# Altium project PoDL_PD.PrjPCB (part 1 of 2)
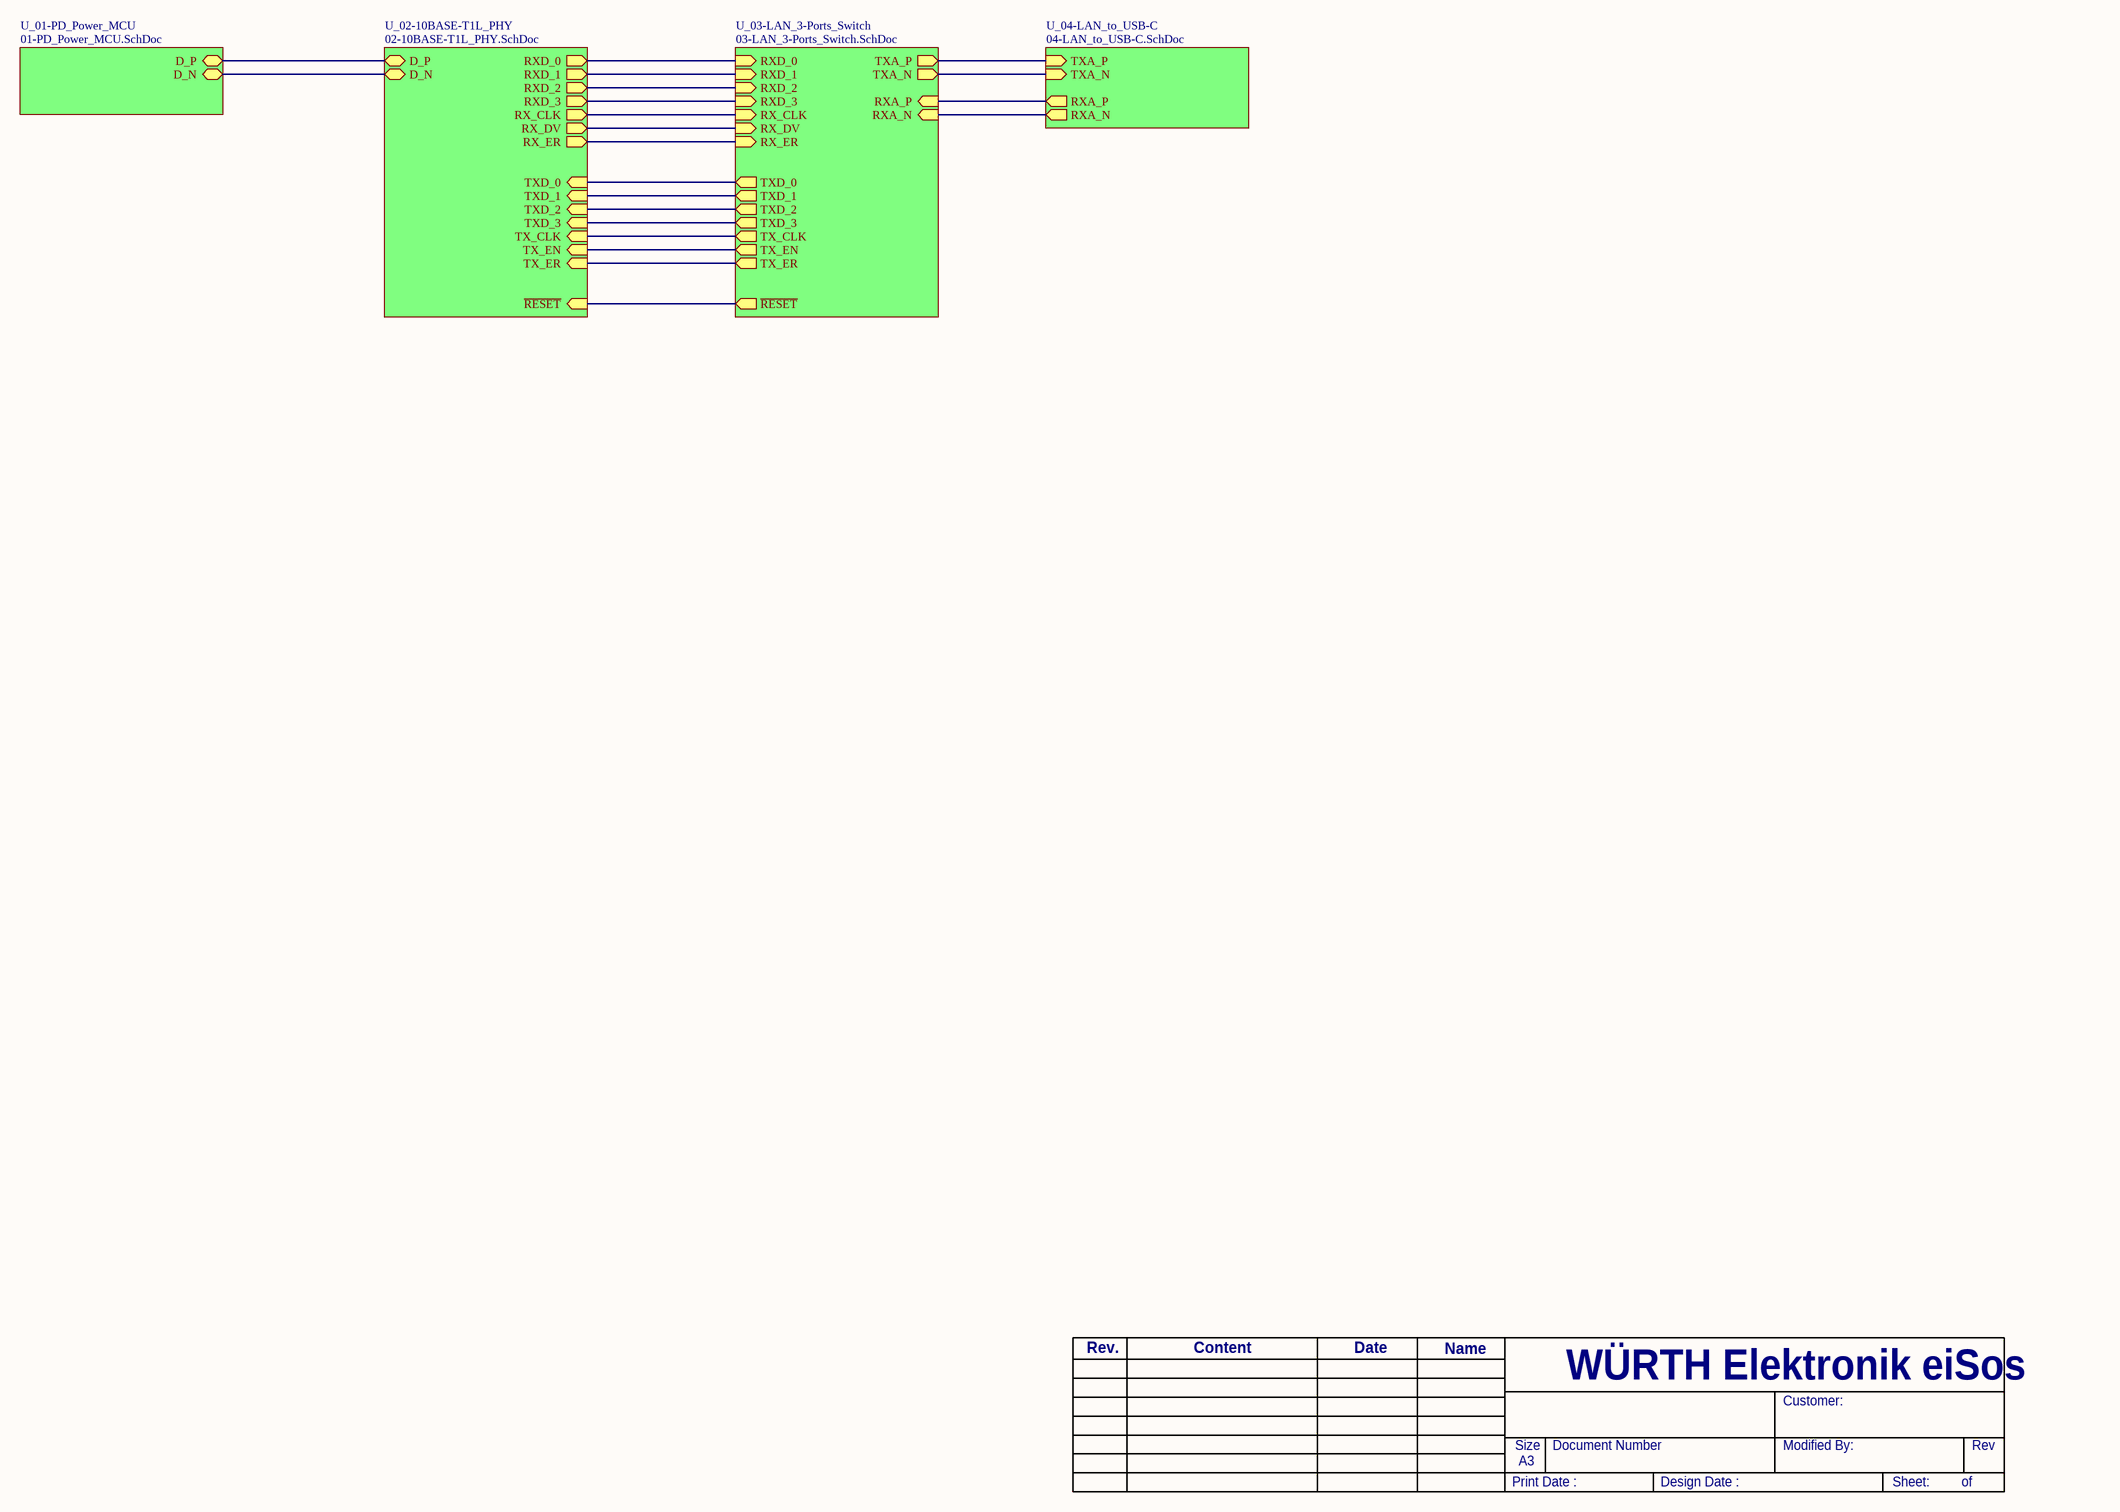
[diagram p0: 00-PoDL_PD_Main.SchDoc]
5 sheets, 346 parts. Net scope: hierarchical (ports join the sheet entries above them; power ports are global).
Board file: PoDL_PD_V15.PcbDoc
Sheets:
  00-PoDL_PD_Main.SchDoc
    U_01-PD_Power_MCU = 01-PD_Power_MCU.SchDoc
    U_02-10BASE-T1L_PHY = 02-10BASE-T1L_PHY.SchDoc
    U_03-LAN_3-Ports_Switch = 03-LAN_3-Ports_Switch.SchDoc
    U_04-LAN_to_USB-C = 04-LAN_to_USB-C.SchDoc

## Sheet 00-PoDL_PD_Main.SchDoc: PD Main
size A2; Date: Mon 1st Aug, 2020; CompanyName: RGT Supply and Service Ltd.; Engineer: Nattawut; Address1: 285/95 M.3 T.Tonpao Sankampaeng; Address2: Chiangmai 50130 Thailand Tel.+66 89 1645339; Revision: 1.5; SheetNumber: 0; SheetTotal: 4; ContentRev1: Original Document; dateREV1: 01-01-2023; NameRev1: Nattawut; NameRev3: Nattawut; NameRev2: Nattawut; NameRev4: Nattawut; NameRev5: Nattawut; NameRev6: Nattawut; dateREV2: 20-04-2023; dateREV3: 04-11-2023; dateREV4: 14-05-2024; dateREV5: 05-07-2024; dateREV6: 16-09-2024; ContentRev2: Change to AD controller; ContentRev3: Update Power Coupling; ContentRev4: Improve for EMC ability; ContentRev5: Add D31, Replace FB7 to R164; ContentRev6: Improve for EMC ability; Rev1: 1.0; Rev2: 1.1; Rev3: 1.2; Rev4: 1.3; Rev5: 1.4; Rev6: 1.5; Project: PoDL; PageSetup: Record=PageOptions¦CenterHorizontal=True¦CenterVertical=True¦PrintScale=0.73¦XCorrection=1.00¦YCorrection=1.00¦PrintKind=0¦BorderSize=5000000¦LeftOffset=0¦BottomOffset=0¦Orientation=2¦PaperLength=1000¦PaperWidth=1000¦Scale=100¦PaperSource=7¦PrintQuality=-3¦MediaType=1¦DitherType=10¦PrintScaleMode=1¦PaperKind=A3¦PaperIndex=8

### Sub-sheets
U_01-PD_Power_MCU = 01-PD_Power_MCU.SchDoc: D_P (bidir), D_N (bidir)
U_02-10BASE-T1L_PHY = 02-10BASE-T1L_PHY.SchDoc: RXD_0 (out), RXD_1 (out), RXD_2 (out), RXD_3 (out), RX_CLK (out), RX_DV (out), RX_ER (out), TX_ER (in), TX_EN (in), TX_CLK (in), TXD_0 (in), TXD_1 (in), TXD_3 (in), TXD_2 (in), ~{RESET} (in), D_P (bidir), D_N (bidir)
U_03-LAN_3-Ports_Switch = 03-LAN_3-Ports_Switch.SchDoc: TXA_N (out), TXA_P (out), RXA_N (in), RXA_P (in), ~{RESET} (out), RXD_1 (in), TXD_2 (out), TXD_3 (out), RX_ER (in), RX_DV (in), RX_CLK (in), RXD_0 (in), RXD_3 (in), TXD_0 (out), TX_EN (out), TX_ER (out), RXD_2 (in), TXD_1 (out), TX_CLK (out)
U_04-LAN_to_USB-C = 04-LAN_to_USB-C.SchDoc: TXA_N (in), TXA_P (in), RXA_N (out), RXA_P (out)

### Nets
D_N: sheet U_01-PD_Power_MCU/D_N, sheet U_02-10BASE-T1L_PHY/D_N
D_P: sheet U_01-PD_Power_MCU/D_P, sheet U_02-10BASE-T1L_PHY/D_P
P0_INCLK: sheet U_02-10BASE-T1L_PHY/RX_CLK, sheet U_03-LAN_3-Ports_Switch/RX_CLK
P0_IND0: sheet U_02-10BASE-T1L_PHY/RXD_0, sheet U_03-LAN_3-Ports_Switch/RXD_0
P0_IND1: sheet U_02-10BASE-T1L_PHY/RXD_1, sheet U_03-LAN_3-Ports_Switch/RXD_1
P0_IND2: sheet U_02-10BASE-T1L_PHY/RXD_2, sheet U_03-LAN_3-Ports_Switch/RXD_2
P0_IND3: sheet U_02-10BASE-T1L_PHY/RXD_3, sheet U_03-LAN_3-Ports_Switch/RXD_3
P0_INDV: sheet U_02-10BASE-T1L_PHY/RX_DV, sheet U_03-LAN_3-Ports_Switch/RX_DV
P0_INER: sheet U_02-10BASE-T1L_PHY/RX_ER, sheet U_03-LAN_3-Ports_Switch/RX_ER
P0_OUT/REF_CLK_MODE0: sheet U_02-10BASE-T1L_PHY/TX_CLK, sheet U_03-LAN_3-Ports_Switch/TX_CLK
P0_OUTD0_MODE1: sheet U_02-10BASE-T1L_PHY/TXD_0, sheet U_03-LAN_3-Ports_Switch/TXD_0
P0_OUTD1_MODE2: sheet U_02-10BASE-T1L_PHY/TXD_1, sheet U_03-LAN_3-Ports_Switch/TXD_1
P0_OUTD2_MODE3: sheet U_02-10BASE-T1L_PHY/TXD_2, sheet U_03-LAN_3-Ports_Switch/TXD_2
P0_OUTD3: sheet U_02-10BASE-T1L_PHY/TXD_3, sheet U_03-LAN_3-Ports_Switch/TXD_3
P0_OUTDV: sheet U_02-10BASE-T1L_PHY/TX_EN, sheet U_03-LAN_3-Ports_Switch/TX_EN
P0_OUTER_SPEED: sheet U_02-10BASE-T1L_PHY/TX_ER, sheet U_03-LAN_3-Ports_Switch/TX_ER
~{RESET}: sheet U_02-10BASE-T1L_PHY/~{RESET}, sheet U_03-LAN_3-Ports_Switch/~{RESET}
RXA_N: sheet U_03-LAN_3-Ports_Switch/RXA_N, sheet U_04-LAN_to_USB-C/RXA_N
RXA_P: sheet U_03-LAN_3-Ports_Switch/RXA_P, sheet U_04-LAN_to_USB-C/RXA_P
TXA_N: sheet U_03-LAN_3-Ports_Switch/TXA_N, sheet U_04-LAN_to_USB-C/TXA_N
TXA_P: sheet U_03-LAN_3-Ports_Switch/TXA_P, sheet U_04-LAN_to_USB-C/TXA_P

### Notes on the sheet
- Rev.
- Content
- Date
- Name
- WÜRTH Elektronik eiSos
- Customer:
- Print Date :
- Size
- A3
- Document Number
- Design Date :
- Modified By:
- Sheet:
- of
- Rev

## Sheet 01-PD_Power_MCU.SchDoc: PD Power & MCU
size A2; Date: Mon 1st Aug, 2020; CompanyName: RGT Supply and Service Ltd.; Engineer: Nattawut; Address1: 285/95 M.3 T.Tonpao Sankampaeng; Address2: Chiangmai 50130 Thailand Tel.+66 89 1645339; Revision: 1.5; SheetNumber: 1; SheetTotal: 4; ContentRev1: Original Document; dateREV1: 01-01-2023; NameRev1: Nattawut; NameRev3: Nattawut; NameRev2: Nattawut; NameRev4: Nattawut; NameRev5: Nattawut; NameRev6: Nattawut; dateREV2: 20-04-2023; dateREV3: 04-11-2023; dateREV4: 14-05-2024; dateREV5: 05-07-2024; dateREV6: 16-09-2024; ContentRev2: Change to AD controller; ContentRev3: Update Power Coupling; ContentRev4: Improve for EMC ability; ContentRev5: Add D31, Replace FB7 to R164; ContentRev6: Improve for EMC ability; Rev1: 1.0; Rev2: 1.1; Rev3: 1.2; Rev4: 1.3; Rev5: 1.4; Rev6: 1.5; Project: PoDL; PageSetup: Record=PageOptions¦CenterHorizontal=True¦CenterVertical=True¦PrintScale=0.73¦XCorrection=1.00¦YCorrection=1.00¦PrintKind=0¦BorderSize=5000000¦LeftOffset=0¦BottomOffset=0¦Orientation=2¦PaperLength=1000¦PaperWidth=1000¦Scale=100¦PaperSource=7¦PrintQuality=-3¦MediaType=1¦DitherType=10¦PrintScaleMode=1¦PaperKind=A3¦PaperIndex=8
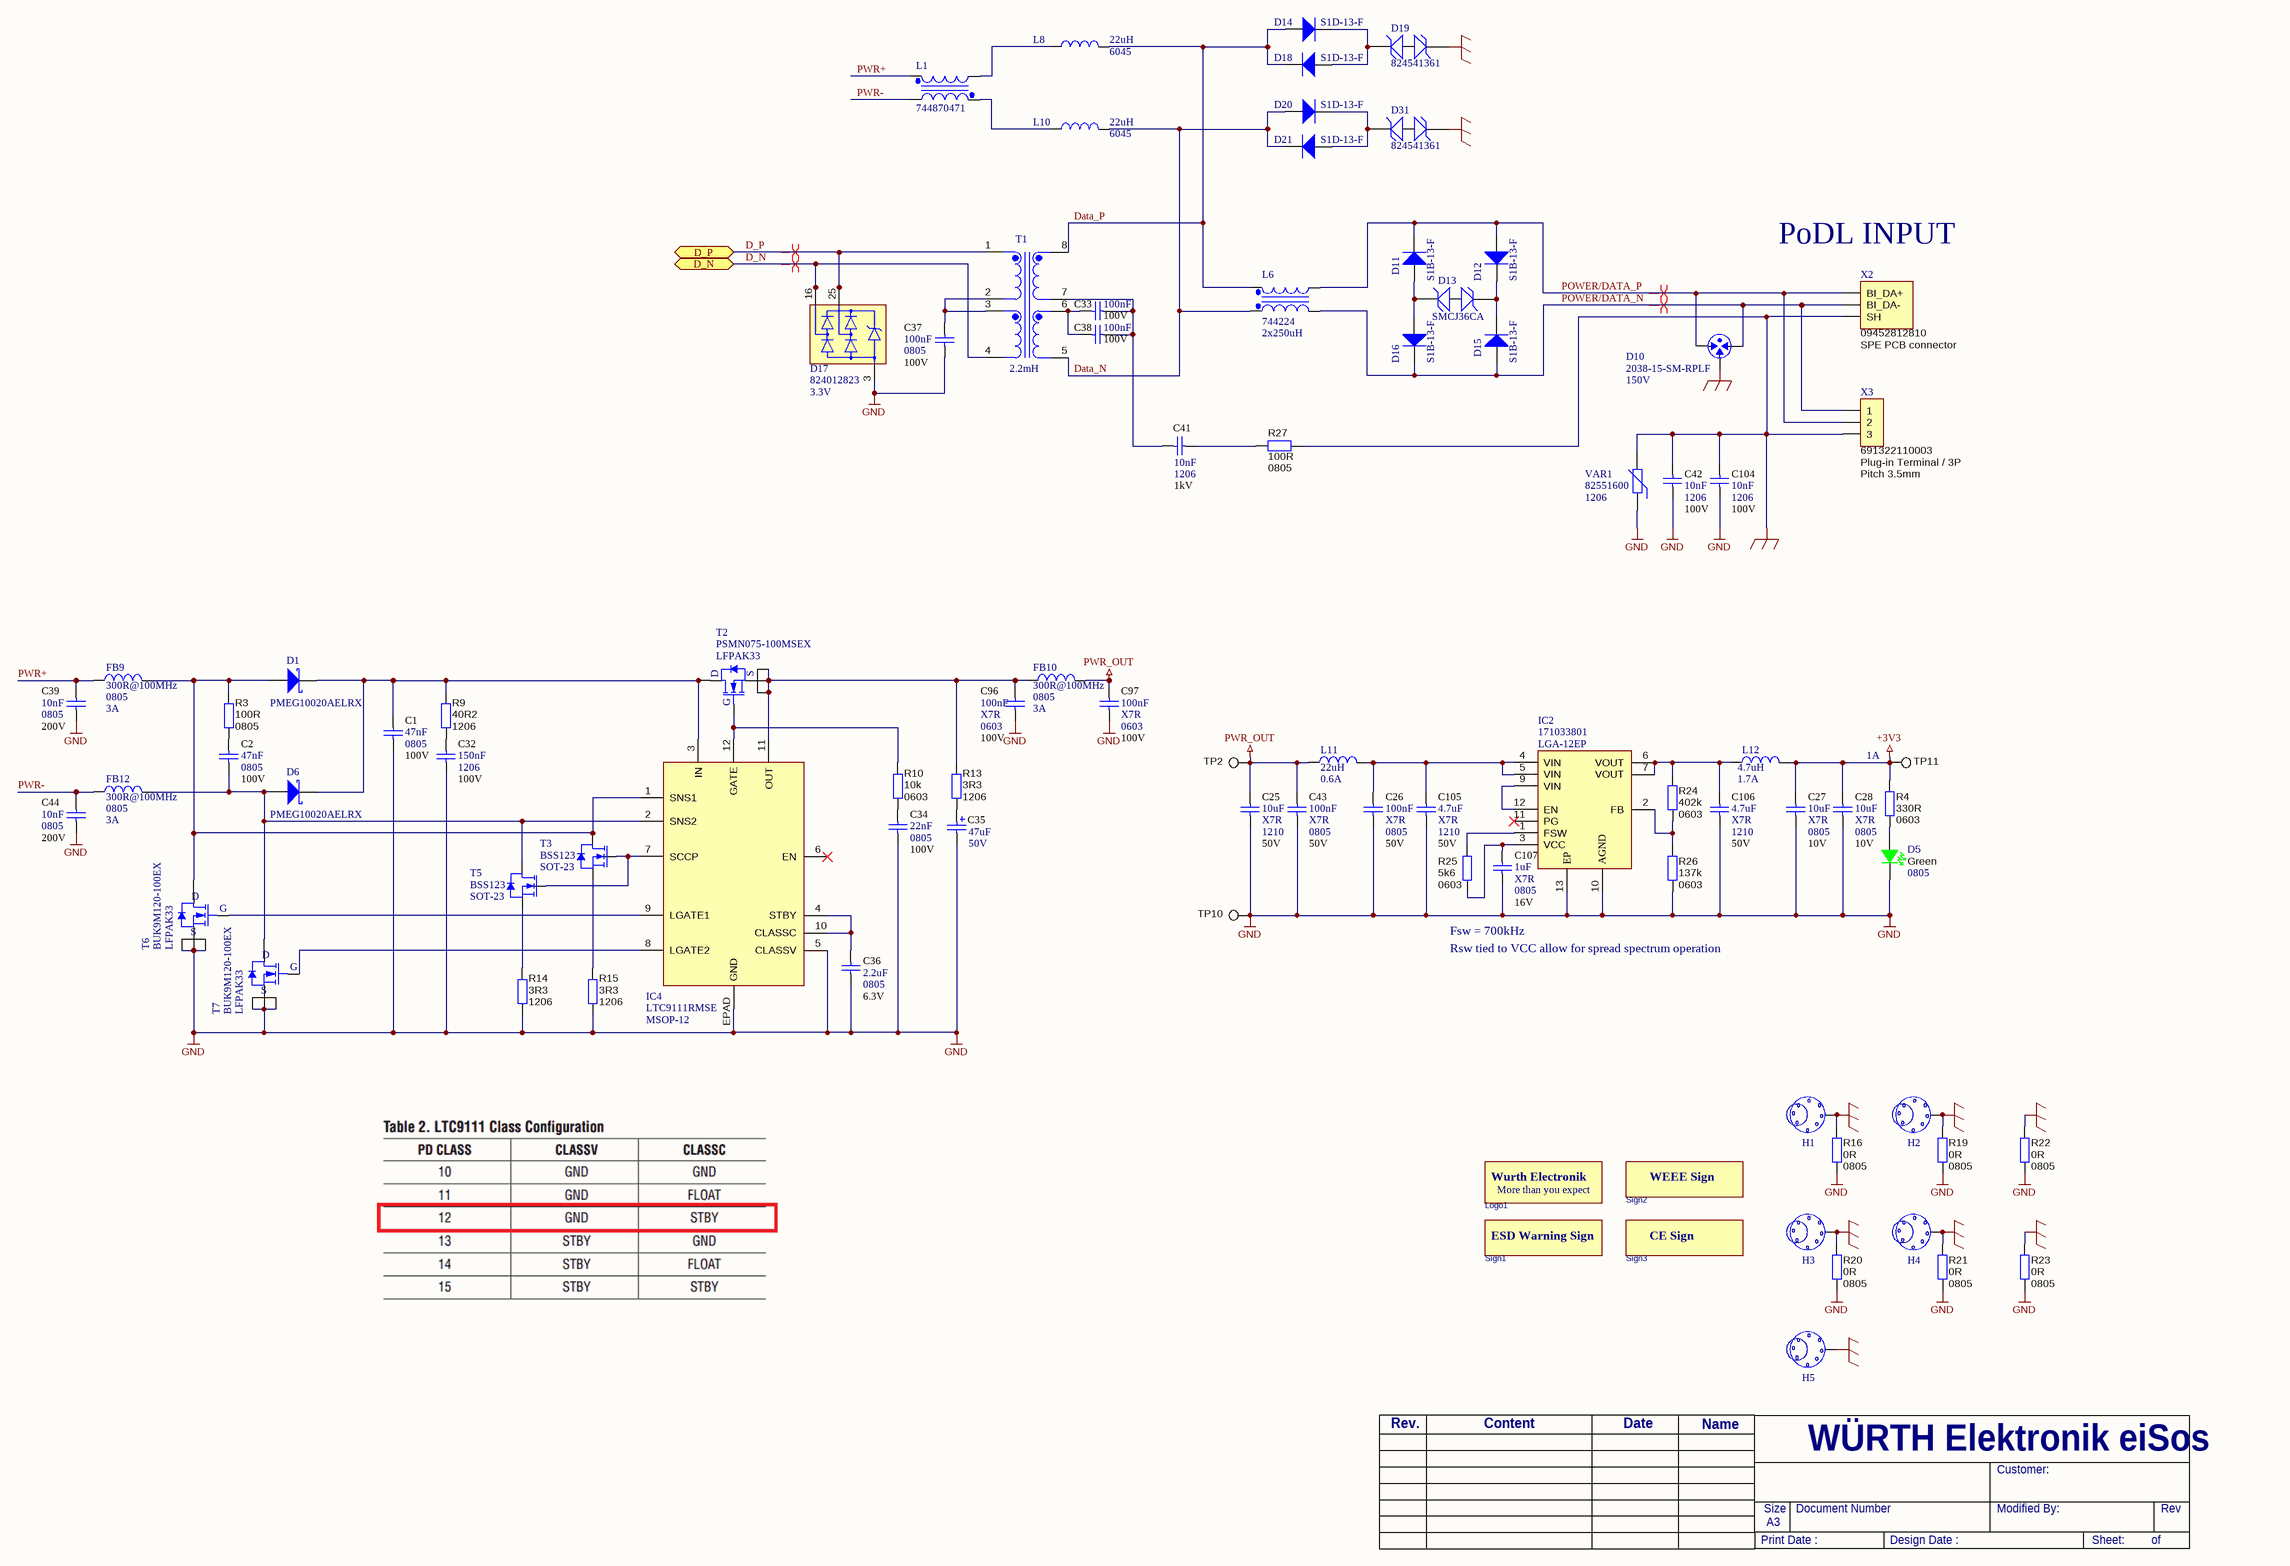
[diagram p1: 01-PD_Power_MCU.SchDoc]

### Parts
C1  value 47nF  VDC_V: 100V  PackageReference: 0805  [CC2012-0805]  (hidden comment: 885012207126)
C2  value 47nF  VDC_V: 100V  PackageReference: 0805  [CC2012-0805]  (hidden comment: 885012207126)
C25  value 10uF  VDC_V: 50V  PackageReference: 1210  Dielectric: X7R  [CC3225-1210]  (hidden comment: 885012209073)
C26  value 100nF  VDC_V: 50V  PackageReference: 0805  Dielectric: X7R  [CC2012-0805]  (hidden comment: 885012207098)
C27  value 10uF  VDC_V: 10V  PackageReference: 0805  Dielectric: X7R  [CC2012-0805]  (hidden comment: 885012207026)
C28  value 10uF  VDC_V: 10V  PackageReference: 0805  Dielectric: X7R  [CC2012-0805]  (hidden comment: 885012207026)
C32  value 150nF  PackageReference: 1206  VDC_V: 100V  [CC3216-1206]  (hidden comment: 885012208119)
C33  value 100nF  VDC_V: 100V  [CC1608-0603]  (hidden comment: 885012206120)
C34  value 22nF  VDC_V: 100V  PackageReference: 0805  [CC2012-0805]  (hidden comment: 885012207124)
C35  value 47uF  VDC_V: 50V  [SMT 6.3mmx7.7mm - WE]  (hidden comment: 865080645012)
C36  value 2.2uF  VDC_V: 6.3V  PackageReference: 0805  [CC2012-0805]  (hidden comment: 885012207001)
C37  value 100nF  VDC_V: 100V  PackageReference: 0805  [CC2012-0805]  (hidden comment: 885012207128)
C38  value 100nF  VDC_V: 100V  [CC1608-0603]  (hidden comment: 885012206120)
C39  value 10nF  VDC_V: 200V  PackageReference: 0805  [CC2012-0805]  (hidden comment: 885342207005)
C41  value 10nF  PackageReference: 1206  VDC_V: 1kV  [CC3216-1206]  (hidden comment: 885342208021)
C42  value 10nF  PackageReference: 1206  VDC_V: 100V  [CC3216-1206]  (hidden comment: 885012208112)
C43  value 100nF  VDC_V: 50V  PackageReference: 0805  Dielectric: X7R  [CC2012-0805]  (hidden comment: 885012207098)
C44  value 10nF  VDC_V: 200V  PackageReference: 0805  [CC2012-0805]  (hidden comment: 885342207005)
C96  value 100nF  VDC_V: 100V  PackageReference: 0603  Dielectric: X7R  [CC1608-0603]  (hidden comment: 885012206120)
C97  value 100nF  VDC_V: 100V  PackageReference: 0603  Dielectric: X7R  [CC1608-0603]  (hidden comment: 885012206120)
C104  value 10nF  PackageReference: 1206  VDC_V: 100V  [CC3216-1206]  (hidden comment: 885012208112)
C105  value 4.7uF  VDC_V: 50V  PackageReference: 1210  Dielectric: X7R  [CC3225-1210]  (hidden comment: 885012209048)
C106  value 4.7uF  VDC_V: 50V  PackageReference: 1210  Dielectric: X7R  [CC3225-1210]  (hidden comment: 885012209048)
C107  value 1uF  VDC_V: 16V  PackageReference: 0805  Dielectric: X7R  [CC2012-0805]  (hidden comment: 885012207051)
D1  PMEG10020AELRX  [SOD-123FL]
D5  value Green  PackageReference: 0805  [LED2012 (0805) - Green]  (hidden comment: 150080VS75000)
D6  PMEG10020AELRX  [SOD-123FL]
D10  value 150V  [2038-xx]  (hidden comment: 2038-15-SM-RPLF)
D11  S1B-13-F  [SMA/DO-214AC]
D12  S1B-13-F  [SMA/DO-214AC]
D13  SMCJ36CA  [SMC/DO-214AB]
D14  S1D-13-F  [SMA/DO-214AC]
D15  S1B-13-F  [SMA/DO-214AC]
D16  S1B-13-F  [SMA/DO-214AC]
D17  Voltage: 3.3V  [DFN1210-6L 1.2X1.0]  (hidden comment: 824012823)
D18  S1D-13-F  [SMA/DO-214AC]
D19  824541361  [SMC/DO-214AB]
D20  S1D-13-F  [SMA/DO-214AC]
D21  S1D-13-F  [SMA/DO-214AC]
D31  824541361  [SMC/DO-214AB]
FB9  value 300R@100MHz  PackageReference: 0805  I DC: 3A  [CF2012-0805]  (hidden comment: 742792031)
FB10  value 300R@100MHz  PackageReference: 0805  I DC: 3A  [CF2012-0805]  (hidden comment: 742792031)
FB12  value 300R@100MHz  PackageReference: 0805  I DC: 3A  [CF2012-0805]  (hidden comment: 742792031)
H1  Hole M3 with Vias  [M3_VIA]  (value not drawn)
H2  Hole M3 with Vias  [M3_VIA]  (value not drawn)
H3  Hole M3 with Vias  [M3_VIA]  (value not drawn)
H4  Hole M3 with Vias  [M3_VIA]  (value not drawn)
H5  Hole M3 with Vias  [M3_VIA]  (value not drawn)
IC2  PackageReference: LGA-12EP  [MAGI³C-VDRM_LGA-12EP]  (hidden comment: 171033801)
IC4  value LTC9111RMSE  PackageReference: MSOP-12  [MSOP-12 PAD]  (hidden comment: LTC9111RMSE#PBF)
L1  PartNumber: 744870471  [Inductor_WE-DD 1280]  (hidden comment: 744870471_(2))
L6  value 2x250uH  [Inductor_WE-SL2]  (hidden comment: 744224)
L8  value 22uH  PackageReference: 6045  [Inductor_WE-LQS 6045]  (hidden comment: 74404064220)
L10  value 22uH  PackageReference: 6045  [Inductor_WE-LQS 6045]  (hidden comment: 74404064220)
L11  value 22uH  I DC: 0.6A  [Inductor_WE-LQS 3015]  (hidden comment: 74404032220)
L12  value 4.7uH  I DC: 1.7A  [Inductor_WE-LQS-4018]  (hidden comment: 74404042047)
Logo1  Wurth_994x400  [Wurth_994x400]  (value not drawn)  (no BOM)
R3  value 100R  PackageReference: 0805  [CR2012-0805]  (hidden comment: 560112120020)
R4  value 330R  PackageReference: 0603  [CR1608-0603]  (hidden comment: 560112116020)
R9  value 40R2  PackageReference: 1206  [CR3216-1206]  (hidden comment: RC1206FR-0740R2L)
R10  value 10k  PackageReference: 0603  [CR1608-0603]  (hidden comment: 560112116005)
R13  value 3R3  PackageReference: 1206  [CR3216-1206]  (hidden comment: RC1206FR-073R3L)
R14  value 3R3  PackageReference: 1206  [CR3216-1206]  (hidden comment: RC1206FR-073R3L)
R15  value 3R3  PackageReference: 1206  [CR3216-1206]  (hidden comment: RC1206FR-073R3L)
R16  value 0R  PackageReference: 0805  [CR2012-0805]  (hidden comment: RC0805JR-070RL)
R19  value 0R  PackageReference: 0805  [CR2012-0805]  (hidden comment: RC0805JR-070RL)
R20  value 0R  PackageReference: 0805  [CR2012-0805]  (hidden comment: RC0805JR-070RL)
R21  value 0R  PackageReference: 0805  [CR2012-0805]  (hidden comment: RC0805JR-070RL)
R22  value 0R  PackageReference: 0805  [CR2012-0805]  (hidden comment: RC0805JR-070RL)
R23  value 0R  PackageReference: 0805  [CR2012-0805]  (hidden comment: RC0805JR-070RL)
R24  value 402k  PackageReference: 0603  [CR1608-0603]  (hidden comment: RC0603FR-07402KL)
R25  value 5k6  PackageReference: 0603  [CR1608-0603]  (hidden comment: 560112116017)
R26  value 137k  PackageReference: 0603  [CR1608-0603]  (hidden comment: RC0603FR-07137KL)
R27  value 100R  PackageReference: 0805  [CR2012-0805]  (hidden comment: 560112120020)
Sign1  ESD_380x350  [ESD_380x351]  (value not drawn)  (no BOM)
Sign2  WEEE_275x400  [WEEE_275x400]  (value not drawn)  (no BOM)
Sign3  CE_412x295  [CE_412x295]  (value not drawn)  (no BOM)
T1  Ind_H: 2.2mH  [749070011_WE-PoDL]  (hidden comment: 749070011)
T2  PackageReference: LFPAK33  [LFPAK33 (SOT1210)]  (hidden comment: PSMN075-100MSEX)
T3  value BSS123  [SOT-23]  (hidden comment: BSS123LT1G)
T5  value BSS123  [SOT-23]  (hidden comment: BSS123LT1G)
T6  PackageReference: LFPAK33  [LFPAK33 (SOT1210)]  (hidden comment: BUK9M120-100EX)
T7  PackageReference: LFPAK33  [LFPAK33 (SOT1210)]  (hidden comment: BUK9M120-100EX)
TP2  (no value)  [TESTPOINT 1.5mm]
TP10  (no value)  [TESTPOINT 1.5mm]
TP11  (no value)  [TESTPOINT 1.5mm]
VAR1  PackageReference: 1206  [CV3216-1206]  (hidden comment: 82551600)
X2  value SPE PCB connector  [09452812810]  (hidden comment: 09452812810)
X3  value Plug-in Terminal / 3P  PackageReference: Pitch 3.5mm  [691322110003]  (hidden comment: 691322110003)

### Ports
D_N (bidir), D_P (bidir)

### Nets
+3V3: C27.1 C28.1 L12.2 R4.1 TP11.1
GND: C1.2 C25.2 C26.2 C27.2 C28.2 C32.2 C34.2 C35.2 C36.2 C37.2 C39.2 C42.2 C43.2 C44.2 C96.2 C97.2 C104.2 C105.2 C106.2 C107.2 D5.1 D17.3(GND) IC2.10(AGND) IC2.13(EP) IC4.5(CLASSV) IC4.EPAD(GND) R14.2 R15.2 R16.1 R19.1 R20.1 R21.1 R22.1 R23.1 R26.2 T6.1(S) T6.2(S) T6.3(S) T7.1(S) T7.2(S) T7.3(S) TP10.1 VAR1.1
PWR_OUT: C25.1 C43.1 C97.1 FB10.2 L11.1 TP2.1
SHIELD: C42.1 C104.1 D10.3 D19.1(A) D31.1(A) H1.0(Hole) H2.0(Hole) H3.0(Hole) H4.0(Hole) H5.0(Hole) R16.2 R19.2 R20.2 R21.2 R22.2 R23.2 R27.2 VAR1.2 X2.SH X3.3
D_N: D17.1(IO1) D17.6(IO1) T1.4 ; port D_N
D_P: D17.2(IO2) D17.5(IO2) T1.1 ; port D_P
Data_N: D20.1(A) D21.2(K) L6.1(L1) L10.2 T1.5
Data_P: D14.1(A) D18.2(K) L6.2(L2) L8.2 T1.8
POWER/DATA_N: D10.2 D15.1(A) D16.2(K) L6.4(L1') X2.2(BI_DA-) X3.1
POWER/DATA_P: D10.1 D11.2(K) D12.1(A) L6.3(L2') X2.1(BI_DA+) X3.2
PWR+: C39.1 FB9.1 L1.1(L1)
PWR-: C44.1 FB12.1 L1.4(L2')
NetC1_1: C1.1 D1.2(K) D6.2(K) IC4.3(IN) R9.1 T2.mb(D)
NetC2_1: C2.1 R3.2
NetC2_2: C2.2 D6.1(A) FB12.2 IC4.2(SNS2) T5.3(D) T7.mb(D)
NetC26_1: C26.1 C105.1 IC2.4(VIN) IC2.5(VIN) L11.2
NetC32_1: C32.1 R9.2
NetC33_1: C33.1 C38.1 T1.6
NetC33_2: C33.2 C38.2 C41.1 T1.7
NetC34_1: C34.1 R10.2
NetC35_1: C35.1 R13.2
NetC36_1: C36.1 IC4.4(STBY) IC4.10(CLASSC)
NetC37_1: C37.1 T1.2 T1.3
NetC41_2: C41.2 R27.1
NetC96_1: C96.1 FB10.1 IC4.11(OUT) R13.1 T2.1(S) T2.2(S) T2.3(S)
NetC106_1: C106.1 IC2.6(VOUT) IC2.7(VOUT) L12.1 R24.2
NetC107_1: C107.1 IC2.3(VCC) R25.2
NetD1_1: D1.1(A) FB9.2 IC4.1(SNS1) R3.1 T3.3(D) T6.mb(D)
NetD5_2: D5.2 R4.2
NetD11_1: D11.1(A) D13.2(K) D16.1(A)
NetD12_2: D12.2(K) D13.1(A) D15.2(K)
NetD14_2: D14.2(K) D18.1(A) D19.2(K)
NetD20_2: D20.2(K) D21.1(A) D31.2(K)
NetIC2_1: IC2.1(FSW) R25.1
NetIC2_2: IC2.2(FB) R24.1 R26.1
NetIC2_9: IC2.9(VIN) IC2.12(EN)
NetIC4_7: IC4.7(SCCP) T3.1(G) T5.1(G)
NetIC4_8: IC4.8(LGATE2) T7.4(G)
NetIC4_9: IC4.9(LGATE1) T6.4(G)
NetIC4_12: IC4.12(GATE) R10.1 T2.4(G)
NetL1_2: L1.2(L2) L10.1
NetL1_3: L1.3(L1') L8.1
NetR14_1: R14.1 T5.2(S)
NetR15_1: R15.1 T3.2(S)

Not connected (* = marked no-connect by the designer): IC2 11(PG)*; IC4 6(EN)*

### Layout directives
differential pair: D_N, D_P, POWER/DATA_N, POWER/DATA_P

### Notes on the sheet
- (near X2) PoDL INPUT
- 1A
- Fsw = 700kHz
- Rsw tied to VCC allow for spread spectrum operation
- Rev.
- Content
- Date
- Name
- WÜRTH Elektronik eiSos
- Customer:
- Print Date :
- Size
- A3
- Document Number
- Design Date :
- Modified By:
- Sheet:
- of
- Rev

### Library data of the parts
C1 C2 = 885012207126: CAP, CERM, 47nF, 100V, +/-10%, X7R, 0805; Manufacturer: Wurth; Polarized: N; TaMax_C: 125; TaMin_C: -55; Tolerance_%: 10; CompType: Capacitor
C25 = 885012209073: CAP, CERM, 10uF, 50V, +/-10%, X7R, 1210; Manufacturer: Wurth; Polarized: N; TaMax_C: 125; TaMin_C: -55; Tolerance_%: 10%; CompType: Capacitor
C26 C43 = 885012207098: CAP, CERM, 100nF, 50V, +/-10%, X7R, 0805; Manufacturer: Wurth; Polarized: N; TaMax_C: 125; TaMin_C: -55; Tolerance_%: 10; CompType: Capacitor
C27 C28 = 885012207026: CAP, CERM, 10uF, 10V, +/-10%, X7R, 0805; Manufacturer: Wurth; Polarized: N; TaMax_C: 125; TaMin_C: -55; Tolerance_%: 10; CompType: Capacitor
C32 = 885012208119: CAP, CERM, 150nF, 100V, +/-10%, X7R, 1206; Manufacturer: Wurth; Polarized: N; TaMax_C: 125; TaMin_C: -55; Tolerance_%: 10; CompType: Capacitor
C33 C38 C96 C97 = 885012206120: CAP, CERM, 100nF, 100V, +/-10%, X7R, 0603; Manufacturer: Wurth; Polarized: N; TaMax_C: 125; TaMin_C: -55; Tolerance_%: 10; CompType: Capacitor
C34 = 885012207124: CAP, CERM, 22nF, 100V, +/-10%, X7R, 0805; Manufacturer: Wurth; Polarized: N; TaMax_C: 125; TaMin_C: -55; Tolerance_%: 10; CompType: Capacitor
C35 = 865080645012: CAP, ECAP, 47uF, 50V, +/-20%, 6.3mm x 7.7mm; Manufacturer: Wurth; ESR_Ohm: -Ohm; IRMS_A: 0.23A; Polarized: Y; TaMax_C: 105; TaMin_C: -55; Tolerance_%: 20; CompType: Capacitor
C36 = 885012207001: CAP, CERM, 2.2uF, 6.3V, +/-10%, X7R, 0805; Manufacturer: Wurth; Polarized: N; TaMax_C: +125; TaMin_C: -55; Tolerance_%: 10; CompType: Capacitor
C37 = 885012207128: CAP, CERM, 100nF, 100V, +/-10%, X7R, 0805; Manufacturer: Wurth; Polarized: N; TaMax_C: 125; TaMin_C: -55; Tolerance_%: 10; CompType: Capacitor
C39 C44 = 885342207005: CAP, CERM, 10nF, 200V, +/-10%, X7R, 0805; Manufacturer: Wurth; Polarized: N; TaMax_C: 125; TaMin_C: -55; Tolerance_%: 10; CompType: Capacitor
C41 = 885342208021: CAP, CERM, 10nF, 1kV, +/-10%, X7R, 1206; Manufacturer: Wurth; Polarized: N; TaMax_C: 125; TaMin_C: -55; Tolerance_%: 10; CompType: Capacitor
C42 C104 = 885012208112: CAP, CERM, 10nF, 100V, +/-10%, X7R, 1206; Manufacturer: Wurth; Polarized: N; TaMax_C: 125; TaMin_C: -55; Tolerance_%: 10; CompType: Capacitor
C105 C106 = 885012209048: CAP, CERM, 4.7uF, 50V, +/-10%, X7R, 1210; Manufacturer: Wurth; Polarized: N; TaMax_C: 125; TaMin_C: -55; Tolerance_%: 10%; CompType: Capacitor
C107 = 885012207051: CAP, CERM, 1uF, 16V, +/-10%, X7R, 0805; Manufacturer: Wurth; Polarized: N; TaMax_C: 125; TaMin_C: -55; Tolerance_%: 10; CompType: Capacitor
D1 D6 = PMEG10020AELRX: DIODE, Schottky, 100V, 2A, SOD-123W; Manufacturer: Nexperia
D5 = 150080VS75000: LED 570NM GREEN 0805 SMD; Manufacturer: Wurth
D10 = 2038-15-SM-RPLF: Gas Discharge Tubes, 150V, 1pF, 5x7.5mm, SMD; Manufacturer: Bourns
D11 D12 D15 D16 = S1B-13-F: DIODE, Rectifiers, 100V, 1A, SMA; Manufacturer: Diodes
D13 = SMCJ36CA: DIODE, TVS , 36V, 1.5kW, Bidirection, SMC; Manufacturer: Onsemi; Power: 1500W
D14 D18 D20 D21 = S1D-13-F: DIODE, Rectifiers, 200V, 1A, SMA; Manufacturer: Diodes
D17 = 824012823: DIODE, TVS Super Speed , 3.3V, DFN1210-6L; Manufacturer: Wurth
D19 D31 = 824541361: DIODE, TVS , 36V, 1.5kW, Bidirection, SMC; Manufacturer: Wurth; Power: 1500W
FB9 FB10 FB12 = 742792031: Ferrite Bead 300R @ 100MHz / 0805 / 3.0A; Manufacturer: Wurth
H1-H5 = Hole M3 with Vias: SAP: xxxx
IC2 = 171033801: IC REG BUCK, ADJ, 3A, LGA-16EP; Manufacturer: Wurth
IC4 = LTC9111RMSE#PBF: IC SPoE PD, 10Base-T1L, 2.3-60V, MSOP-12; Manufacturer: Analog Devices
L1 = 744870471_(2): Coupled Inductor 2x470uH / 12.5x12.5mm /0.7A; Manufacturer: Wurth; Rdc: 2x1.0; I DC: 0.7A
L6 = 744224: Common Mode Chokes 2x250uH / 9.2x6mm / 1200mA; Manufacturer: Wurth; Rdc: 0.13; I DC: 1.2A
L8 L10 = 74404064220: Inductor 22uH / 6045 / 2.1A; Manufacturer: Wurth
L11 = 74404032220: Inductor 22uH / 3015 / 0.6A; Manufacturer: Wurth
L12 = 74404042047: Inductor 4.7uH / 4018 / 1.7A; Manufacturer: Wurth
R3 R27 = 560112120020: RES, 100 ohm, 1%, 0.125W, 0805; Manufacturer: Wurth; CompType: Resistor; Power_W: 0.125
R4 = 560112116020: RES, 330 ohm, 1%, 0.1W, 0603; Manufacturer: Wurth; CompType: Resistor; Power_W: 0.1
R9 = RC1206FR-0740R2L: RES, 40.2 ohm, 1%, 0.25W, 1206; Manufacturer: Yageo; CompType: Resistor; Power_W: 0.25
R10 = 560112116005: RES, 10kohm, 1%, 0.1W, 0603; Manufacturer: Wurth; CompType: Resistor; Power_W: 0.1
R13-R15 = RC1206FR-073R3L: RES, 3.3 ohm, 1%, 0.25W, 1206; Manufacturer: Yageo; CompType: Resistor; Power_W: 0.25
R16 R19-R23 = RC0805JR-070RL: RES, 0 ohm, -%, 0.125W, 0805; Manufacturer: Yageo; CompType: Resistor; Power_W: 0.125
R24 = RC0603FR-07402KL: RES, 402kohm, 1%, 0.1W, 0603; Manufacturer: Yageo; CompType: Resistor; Power_W: 0.1
R25 = 560112116017: RES, 5.6kohm, 1%, 0.1W, 0603; Manufacturer: Wurth; CompType: Resistor; Power_W: 0.1
R26 = RC0603FR-07137KL: RES, 137kohm, 1%, 0.1W, 0603; Manufacturer: Yageo; CompType: Resistor; Power_W: 0.1
T1 = 749070011: Trans, PoDL, 2.2mH, SMT; Manufacturer: Wurth; CompType: Transformer; Ns1toNp: 1:1
T2 = PSMN075-100MSEX: MOSFET, N-CH, 100V, 18A, LFPAK33; Manufacturer: Nexperia
T3 T5 = BSS123LT1G: MOSFET, N-CH, 100V, 0.17A, SOT-23; Manufacturer: Onsemi
T6 T7 = BUK9M120-100EX: MOSFET, N-CH, 100V, 11.5A, LFPAK33; Manufacturer: Nexperia
TP2 TP10 TP11 = TP / 1.5mm: Test Point, SMT, Miniature; Value: 1.5mm
VAR1 = 82551600: Varistor, 85Vdc, 60Vac, 160pF, 1206; Manufacturer: Wurth
X2 = 09452812810: CON, SPE, 2P, Shield, 4A, R/A, INS; Manufacturer: HARTING; CompType: Connector
X3 = 691322110003: CON, Terminal Block, Plug-in, 3P, P3.5mm, 10A, R/A, INS; Manufacturer: Wurth; CompType: Connector

## Sheet 02-10BASE-T1L_PHY.SchDoc: ADIN1100 10BASE-T1L PHY
size A2; Date: Mon 1st Aug, 2020; CompanyName: RGT Supply and Service Ltd.; Engineer: Nattawut; Address1: 285/95 M.3 T.Tonpao Sankampaeng; Address2: Chiangmai 50130 Thailand Tel.+66 89 1645339; Revision: 1.5; SheetNumber: 2; SheetTotal: 4; ContentRev1: Original Document; dateREV1: 01-01-2023; NameRev1: Nattawut; NameRev3: Nattawut; NameRev2: Nattawut; NameRev4: Nattawut; NameRev5: Nattawut; NameRev6: Nattawut; dateREV2: 20-04-2023; dateREV3: 04-11-2023; dateREV4: 14-05-2024; dateREV5: 05-07-2024; dateREV6: 16-09-2024; ContentRev2: Change to AD controller; ContentRev3: Update Power Coupling; ContentRev4: Improve for EMC ability; ContentRev5: Add D31, Replace FB7 to R164; ContentRev6: Improve for EMC ability; Rev1: 1.0; Rev2: 1.1; Rev3: 1.2; Rev4: 1.3; Rev5: 1.4; Rev6: 1.5; Project: PoDL; PageSetup: Record=PageOptions¦CenterHorizontal=True¦CenterVertical=True¦PrintScale=0.73¦XCorrection=1.00¦YCorrection=1.00¦PrintKind=0¦BorderSize=5000000¦LeftOffset=0¦BottomOffset=0¦Orientation=2¦PaperLength=1000¦PaperWidth=1000¦Scale=100¦PaperSource=7¦PrintQuality=-3¦MediaType=1¦DitherType=10¦PrintScaleMode=1¦PaperKind=A3¦PaperIndex=8
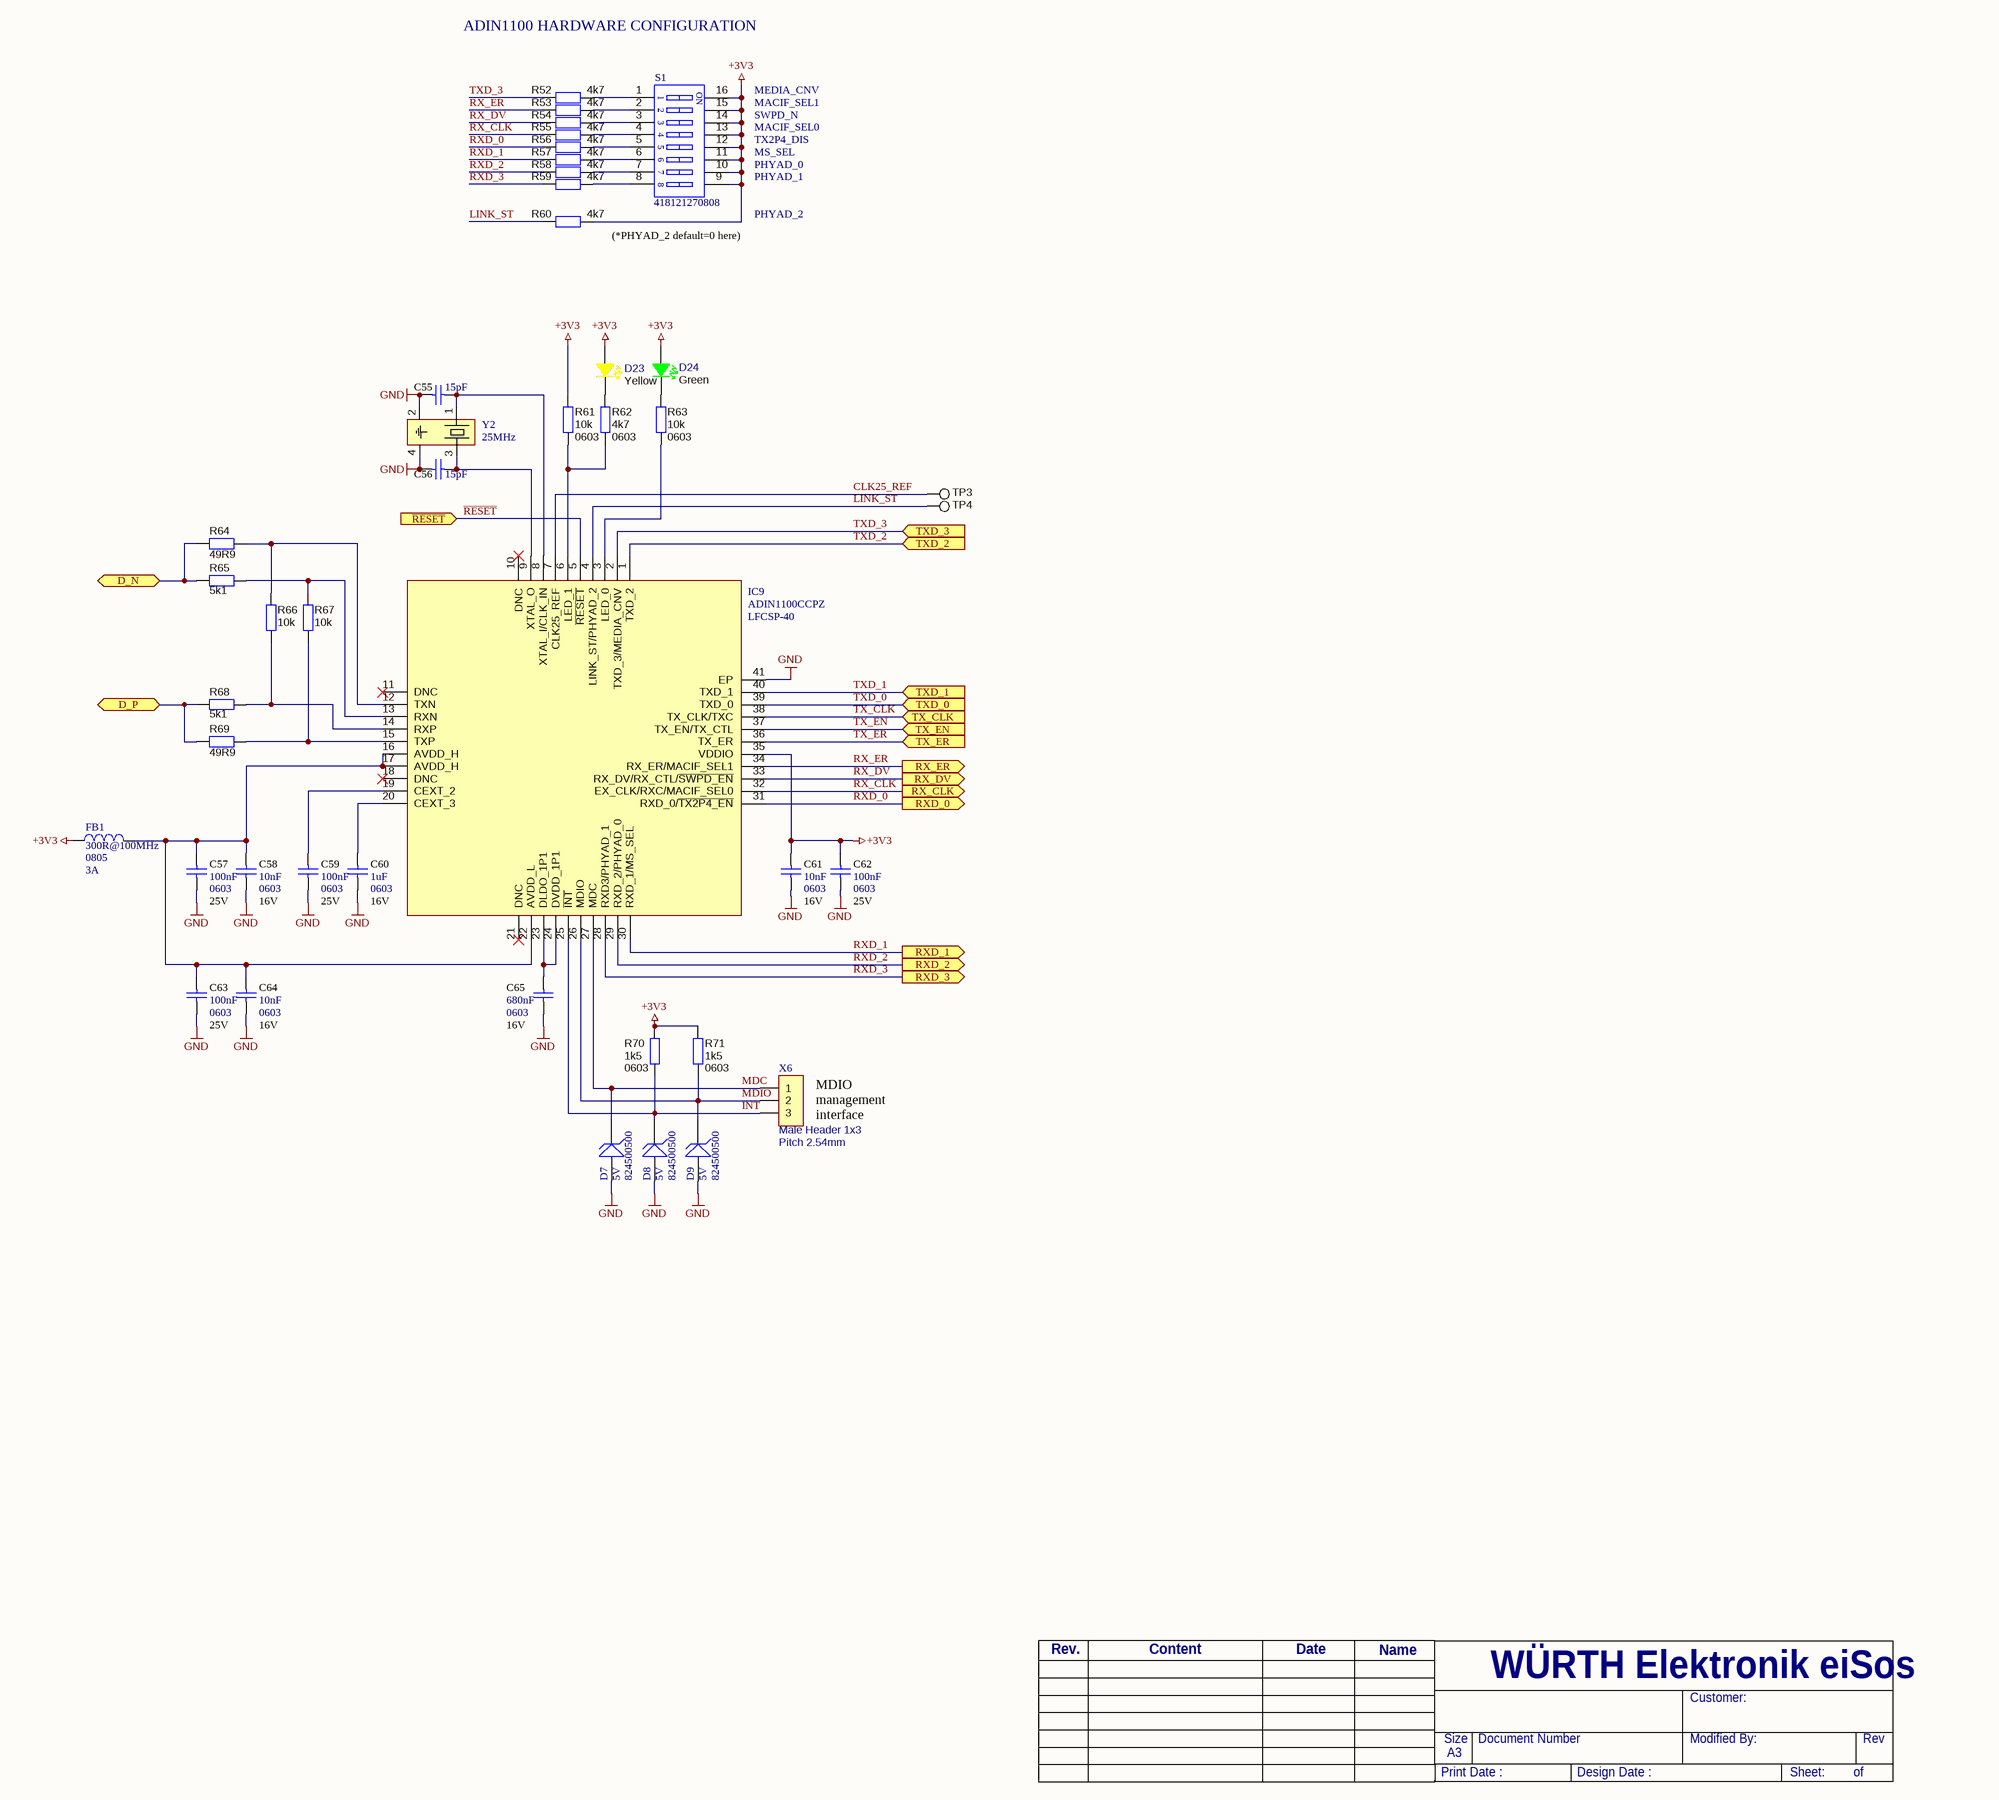
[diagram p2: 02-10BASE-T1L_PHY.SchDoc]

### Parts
C55  value 15pF  [CC1005-0402]  (hidden comment: 885012005056)
C56  value 15pF  [CC1005-0402]  (hidden comment: 885012005056)
C57  value 100nF  VDC_V: 25V  PackageReference: 0603  [CC1608-0603]  (hidden comment: 885012206071)
C58  value 10nF  VDC_V: 16V  PackageReference: 0603  [CC1608-0603]  (hidden comment: 885012206040)
C59  value 100nF  VDC_V: 25V  PackageReference: 0603  [CC1608-0603]  (hidden comment: 885012206071)
C60  value 1uF  VDC_V: 16V  PackageReference: 0603  [CC1608-0603]  (hidden comment: 885012206052)
C61  value 10nF  VDC_V: 16V  PackageReference: 0603  [CC1608-0603]  (hidden comment: 885012206040)
C62  value 100nF  VDC_V: 25V  PackageReference: 0603  [CC1608-0603]  (hidden comment: 885012206071)
C63  value 100nF  VDC_V: 25V  PackageReference: 0603  [CC1608-0603]  (hidden comment: 885012206071)
C64  value 10nF  VDC_V: 16V  PackageReference: 0603  [CC1608-0603]  (hidden comment: 885012206040)
C65  value 680nF  VDC_V: 16V  PackageReference: 0603  [CC1608-0603]  (hidden comment: 885012206051)
D7  Voltage: 5V  [SMA/DO-214AC]  (hidden comment: 824500500)
D8  Voltage: 5V  [SMA/DO-214AC]  (hidden comment: 824500500)
D9  Voltage: 5V  [SMA/DO-214AC]  (hidden comment: 824500500)
D23  value Yellow  [LED1608 (0603) - YELLOW]  (hidden comment: LTST-C190KSKT)
D24  value Green  [LED1608 (0603) - Green]  (hidden comment: 150060VS75020)
FB1  value 300R@100MHz  PackageReference: 0805  I DC: 3A  [CF2012-0805]  (hidden comment: 742792031)
IC9  value ADIN1100CCPZ  PackageReference: LFCSP-40  [QFN-40 6x6MM]  (hidden comment: ADIN1100CCPZ-R7)
R52  value 4k7  [CR1608-0603]  (hidden comment: 560112116006)
R53  value 4k7  [CR1608-0603]  (hidden comment: 560112116006)
R54  value 4k7  [CR1608-0603]  (hidden comment: 560112116006)
R55  value 4k7  [CR1608-0603]  (hidden comment: 560112116006)
R56  value 4k7  [CR1608-0603]  (hidden comment: 560112116006)
R57  value 4k7  [CR1608-0603]  (hidden comment: 560112116006)
R58  value 4k7  [CR1608-0603]  (hidden comment: 560112116006)
R59  value 4k7  [CR1608-0603]  (hidden comment: 560112116006)
R60  value 4k7  [CR1608-0603]  (hidden comment: 560112116006)
R61  value 10k  PackageReference: 0603  [CR1608-0603]  (hidden comment: 560112116005)
R62  value 4k7  PackageReference: 0603  [CR1608-0603]  (hidden comment: 560112116006)
R63  value 10k  PackageReference: 0603  [CR1608-0603]  (hidden comment: 560112116005)
R64  value 49R9  [CR1608-0603]  (hidden comment: 560112116133)
R65  value 5k1  [CR1608-0603]  (hidden comment: RC0603FR-075K1L)
R66  value 10k  [CR1608-0603]  (hidden comment: 560112116005)
R67  value 10k  [CR1608-0603]  (hidden comment: 560112116005)
R68  value 5k1  [CR1608-0603]  (hidden comment: RC0603FR-075K1L)
R69  value 49R9  [CR1608-0603]  (hidden comment: 560112116133)
R70  value 1k5  PackageReference: 0603  [CR1608-0603]  (hidden comment: 560112116038)
R71  value 1k5  PackageReference: 0603  [CR1608-0603]  (hidden comment: 560112116038)
S1  418121270808  [418121270808]
TP3  (no value)  [TESTPOINT 1.5mm]
TP4  (no value)  [TESTPOINT 1.5mm]
X6  value Male Header 1x3  PackageReference: Pitch 2.54mm  [HDR1X3]  (hidden comment: 61300311121)
Y2  value 25MHz  [CRYSTAL_3225]  (hidden comment: 830055299)

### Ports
D_N (bidir), D_P (bidir), RX_CLK (out), RX_DV (out), RX_ER (out), RXD_0 (out), RXD_1 (out), RXD_2 (out), RXD_3 (out), TX_CLK (in), TX_EN (in), TX_ER (in), TXD_0 (in), TXD_1 (in), TXD_2 (in), TXD_3 (in), ~{RESET} (in)

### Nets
+3V3: C61.1 C62.1 D23.2 D24.2 FB1.1 IC9.35(VDDIO) R60.2 R61.2 R70.1 R71.1 S1.9(A9) S1.10(A10) S1.11(A11) S1.12(A12) S1.13(A13) S1.14(A14) S1.15(A15) S1.16(A16)
GND: C55.1 C56.1 C57.2 C58.2 C59.2 C60.2 C61.2 C62.2 C63.2 C64.2 C65.2 D7.1(A) D8.1(A) D9.1(A) IC9.41(EP) Y2.2 Y2.4
CLK25_REF: IC9.7(CLK25_REF) TP3.1
D_N: R64.1 R65.1 ; port D_N
D_P: R68.1 R69.1 ; port D_P
~{INT}: D8.2(K) IC9.25(~{INT}) R70.2 X6.3
LINK_ST: IC9.4(LINK_ST/PHYAD_2) R60.1 TP4.1
MDC: D7.2(K) IC9.27(MDC) X6.1
MDIO: D9.2(K) IC9.26(MDIO) R71.2 X6.2
~{RESET}: IC9.5(~{RESET}) ; port ~{RESET}
RX_CLK: IC9.32(EX_CLK/RXC/MACIF_SEL0) R55.1 ; port RX_CLK  [project net P0_INCLK]
RX_DV: IC9.33(RX_DV/RX_CTL/~{SWPD_EN}) R54.1 ; port RX_DV  [project net P0_INDV]
RX_ER: IC9.34(RX_ER/MACIF_SEL1) R53.1 ; port RX_ER  [project net P0_INER]
RXD_0: IC9.31(RXD_0/~{TX2P4_EN}) R56.1 ; port RXD_0  [project net P0_IND0]
RXD_1: IC9.30(RXD_1/MS_SEL) R57.1 ; port RXD_1  [project net P0_IND1]
RXD_2: IC9.29(RXD_2/PHYAD_0) R58.1 ; port RXD_2  [project net P0_IND2]
RXD_3: IC9.28(RXD3/PHYAD_1) R59.1 ; port RXD_3  [project net P0_IND3]
TX_CLK: IC9.38(TX_CLK/TXC) ; port TX_CLK  [project net P0_OUT/REF_CLK_MODE0]
TX_EN: IC9.37(TX_EN/TX_CTL) ; port TX_EN  [project net P0_OUTDV]
TX_ER: IC9.36(TX_ER) ; port TX_ER  [project net P0_OUTER_SPEED]
TXD_0: IC9.39(TXD_0) ; port TXD_0  [project net P0_OUTD0_MODE1]
TXD_1: IC9.40(TXD_1) ; port TXD_1  [project net P0_OUTD1_MODE2]
TXD_2: IC9.1(TXD_2) ; port TXD_2  [project net P0_OUTD2_MODE3]
TXD_3: IC9.2(TXD_3/MEDIA_CNV) R52.1 ; port TXD_3  [project net P0_OUTD3]
NetC55_2: C55.2 IC9.8(XTAL_I/CLK_IN) Y2.1
NetC56_2: C56.2 IC9.9(XTAL_O) Y2.3
NetC57_1: C57.1 C58.1 C63.1 C64.1 FB1.2 IC9.16(AVDD_H) IC9.17(AVDD_H) IC9.22(AVDD_L)
NetC59_1: C59.1 IC9.19(CEXT_2)
NetC60_1: C60.1 IC9.20(CEXT_3)
NetC65_1: C65.1 IC9.23(DLDO_1P1) IC9.24(DVDD_1P1)
NetD23_1: D23.1 R62.1
NetD24_1: D24.1 R63.2
NetIC9_3: IC9.3(LED_0) R63.1
NetIC9_6: IC9.6(LED_1) R61.1 R62.2
NetIC9_12: IC9.12(TXN) R64.2 R66.1
NetIC9_13: IC9.13(RXN) R65.2 R67.1
NetIC9_14: IC9.14(RXP) R66.2 R68.2
NetIC9_15: IC9.15(TXP) R67.2 R69.2
NetR52_2: R52.2 S1.1(A1)
NetR53_2: R53.2 S1.2(A2)
NetR54_2: R54.2 S1.3(A3)
NetR55_2: R55.2 S1.4(A4)
NetR56_2: R56.2 S1.5(A5)
NetR57_2: R57.2 S1.6(A6)
NetR58_2: R58.2 S1.7(A7)
NetR59_2: R59.2 S1.8(A8)

Not connected (* = marked no-connect by the designer): IC9 10(DNC)* 11(DNC)* 18(DNC)* 21(DNC)*

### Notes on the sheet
- ADIN1100 HARDWARE CONFIGURATION
- MEDIA_CNV
- MACIF_SEL1
- SWPD_N
- MACIF_SEL0
- TX2P4_DIS
- MS_SEL
- PHYAD_0
- PHYAD_1
- PHYAD_2
- (*PHYAD_2 default=0 here)
- (near X6) MDIO
  management
  interface
- Rev.
- Content
- Date
- Name
- WÜRTH Elektronik eiSos
- Customer:
- Print Date :
- Size
- A3
- Document Number
- Design Date :
- Modified By:
- Sheet:
- of
- Rev

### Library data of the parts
C55 C56 = 885012005056: CAP, CERM, 15pF, 50V, +/-5%, C0G, 0402; Manufacturer: Wurth; Polarized: N; TaMax_C: 125; TaMin_C: -55; Tolerance_%: 5; CompType: Capacitor
C57 C59 C62 C63 = 885012206071: CAP, CERM, 100nF, 25V, +/-10%, X7R, 0603; Manufacturer: Wurth; Polarized: N; TaMax_C: 125; TaMin_C: -55; Tolerance_%: 10; CompType: Capacitor
C58 C61 C64 = 885012206040: CAP, CERM, 10nF, 16V, +/-10%, X7R, 0603; Manufacturer: Wurth; Polarized: N; TaMax_C: 125; TaMin_C: -55; Tolerance_%: 10; CompType: Capacitor
C60 = 885012206052: CAP, CERM, 1uF, 16V, +/-10%, X7R, 0603; Manufacturer: Wurth; Polarized: N; TaMax_C: 125; TaMin_C: -55; Tolerance_%: 10%; CompType: Capacitor
C65 = 885012206051: CAP, CERM, 680nF, 16V, +/-10%, X7R, 0603; Manufacturer: Wurth; Polarized: N; TaMax_C: 125; TaMin_C: -55; Tolerance_%: 10; CompType: Capacitor
D7-D9 = 824500500: DIODE, TVS , 5V, 400W, Unidirection, SMA; Manufacturer: Wurth
D23 = LTST-C190KSKT: LED 587NM YELLOW 0603 SMD; Manufacturer: Lite-On Inc.
D24 = 150060VS75020: LED 572NM GREEN 0603 SMD; Manufacturer: Wurth
FB1 = 742792031: as FB9 on sheet 01-PD_Power_MCU
IC9 = ADIN1100CCPZ-R7: IC Ethernet 10BASE-T1L PHY, 3.3V, LFCSP-40; Manufacturer: Microchip
R52-R60 R62 = 560112116006: RES, 4.7kohm, 1%, 0.1W, 0603; Manufacturer: Wurth; CompType: Resistor; Power_W: 0.1
R61 R63 R66 R67 = 560112116005: as R10 on sheet 01-PD_Power_MCU
R64 R69 = 560112116133: RES, 49.9 ohm, 1%, 0.1W, 0603; Manufacturer: Wurth; CompType: Resistor; Power_W: 0.1
R65 R68 = RC0603FR-075K1L: RES, 5.1kohm, 1%, 0.1W, 0603; Manufacturer: Yageo; CompType: Resistor; Power_W: 0.1
R70 R71 = 560112116038: RES, 1.5kohm, 1%, 0.1W, 0603; Manufacturer: Wurth; CompType: Resistor; Power_W: 0.1
S1 = 418121270808: DIP SWITCH, SPST, 0.025A, 24V; Manufacturer: Wurth
TP3 TP4 = TP / 1.5mm: Test Point, SMT, Miniature; Value: 1.5mm
X6 = 61300311121: CON, Header, Male, 3P, P2.54mm, Straight, INS; Manufacturer: Wurth; CompType: Connector
Y2 = 830055299: Crystal / 25MHz / 18pF / 30ppm; Manufacturer: Wurth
